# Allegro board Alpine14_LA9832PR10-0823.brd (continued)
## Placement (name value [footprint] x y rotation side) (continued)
PU1  -  [TS5A63157DCKR_SC70-6]  125.72 122.65 180 top
PU51  -  [TPS51225CRUKR_QFN20_3X3]  188.92 143.86 270 top
PU100  -  [G5616ARZ1U_TQFN20_3X3]  175.97 83.47 180 top
PU150  -  [TPS51362RVER_QFN28_4P5X3P5]  150.59 77.32 90 bottom
PU200  -  [SYN470DBC_DFN10_3X3]  267.32 168.04 0 bottom
PU300  -  [TPS51622RSM_QFN32_4X4]  52.87 19.74 270 bottom
PU301  -  [CSD97374CQ4M_SON8_3P5X4P5]  68.88 26.48 270 bottom
PU401  -  [INA199A1DCKR_SC70-6]  116.07 130.98 90 top
PU402  -  [BQ24717RGRR_QFN20_3P5X3P5]  109.84 143.68 0 top
PU403  -  [LM358DR2G_SO8]  109.71 127.91 90 top
PU404  -  [LM393DR_SO8]  112.16 121.47 90 top
PU405  -  [74AHC1G08GW_SOT353-5]  121.32 118.15 90 top
PU500  -  [74AHC1G08GW_SOT353-5]  137.2 131.45 270 top
PU502  -  [74AHC1G08GW_SOT353-5]  140.5 127.64 270 top
PU503  -  [74AHC1G08GW_SOT353-5]  144.86 149.54 0 top
PU504  -  [74AHC1G08GW_SOT353-5]  145.5 152.71 0 top
PU505  -  [74AHC1G08GW_SOT353-5]  141.94 152.71 0 top
PU506  -  [74AHC1G08GW_SOT353-5]  145.76 129.11 0 top
PU600  -  [RT8813AGQW_WQFN24_4X4]  58.46 36.55 270 bottom
PU700  RT8237EZQW(2)_WDFN10_3X3  [RT8237EZQW-2_WDFN10_3X3]  34.68 30.04 90 bottom
PU701  -  [CD3301BRHHR_QFN36_6X6]  121.03 135.77 0 top
Q5  DMN66D0LDW-7_SOT363-6~D  [DMN66D0LDW-7_SOT363-6]  174.61 107.18 180 top
Q9  -  [L2N7002WT1G_SC-70-3]  135.93 116.89 90 top
Q11  PMST3904_SOT323-3~D  [PMST3904_SOT323-3]  116.05 42.5 180 top
Q12  MMST3904-7-F_SOT323-3~D  [MMST3904-7-F_SOT323-3]  149.9 115.5 270 top
Q13  PMST3904_SOT323-3~D  [PMST3904_SOT323-3]  76.05 78.38 180 top
Q14  PMST3904_SOT323-3~D  [PMST3904_SOT323-3]  166.84 142.17 0 top
Q15  PMST3904_SOT323-3~D  [PMST3904_SOT323-3]  174.28 79.25 180 bottom
Q16  PDTA114EU_SC70-3~D  [PDTA114EU_SC70-3]  177.46 8.6 0 top
Q19  DMN66D0LDW-7_SOT363-6~D  [DMN66D0LDW-7_SOT363-6]  84.38 110.92 180 top
Q20  -  [L2N7002WT1G_SC-70-3]  261.09 159.31 270 bottom
Q21  DMN66D0LDW-7_SOT363-6~D  [DMN66D0LDW-7_SOT363-6]  264.31 158.67 0 bottom
Q22  DMN66D0LDW-7_SOT363-6~D  [DMN66D0LDW-7_SOT363-6]  225.78 151.49 90 bottom
Q24  DMN66D0LDW-7_SOT363-6~D  [DMN66D0LDW-7_SOT363-6]  172.88 2.9 90 top
Q26  PDTA114EU_SC70-3~D  [PDTA114EU_SC70-3]  179.33 4.25 90 top
Q28  DMN66D0LDW-7_SOT363-6~D  [DMN66D0LDW-7_SOT363-6]  190.98 88.84 270 top
Q30  DMN66D0LDW-7_SOT363-6~D  [DMN66D0LDW-7_SOT363-6]  227.68 150.18 270 bottom
Q32  DMN66D0LDW-7_SOT363-6~D  [DMN66D0LDW-7_SOT363-6]  192.84 156.71 180 top
Q122  DMN66D0LDW-7_SOT363-6~D  [DMN66D0LDW-7_SOT363-6]  19.08 102.72 90 top
Q123  DMN66D0LDW-7_SOT363-6~D  [DMN66D0LDW-7_SOT363-6]  247.17 148.6 270 bottom
Q124  SI3457CDV-T1-GE3_TSOP6~D  [SI3457CDV-T1-GE3_TSOP6]  86.46 159.09 0 bottom
Q125  DMN66D0LDW-7_SOT363-6~D  [DMN66D0LDW-7_SOT363-6]  88.43 161.87 270 bottom
Q126  -  [LP2301ALT1G_SOT23-3]  101.35 144.01 90 top
Q133  NTS4001NT1G_SC70-3  [BSS138W-7-F_SOT323-3]  149.32 147.95 270 top
Q135  NTS4001NT1G_SC70-3  [BSS138W-7-F_SOT323-3]  155.61 148.07 270 top
Q137  -  [LP2301ALT1G_SOT23-3]  72.49 107.93 0 top
Q138  -  [LP2301ALT1G_SOT23-3]  77.68 103.05 0 bottom
Q140  DMN66D0LDW-7_SOT363-6~D  [DMN66D0LDW-7_SOT363-6]  74.9 107.45 270 bottom
Q142  -  [SI3456DDV-T1-GE3_TSOP6]  95.27 75.55 270 top
Q143  DMN66D0LDW-7_SOT363-6~D  [DMN66D0LDW-7_SOT363-6]  94.97 83.95 270 top
QC1  DMN66D0LDW-7_SOT363-6~D  [DMN66D0LDW-7_SOT363-6]  119.99 83 270 top
QC4  DMN66D0LDW-7_SOT363-6~D  [DMN66D0LDW-7_SOT363-6]  167.69 123.93 90 top
QC6  DMN66D0LDW-7_SOT363-6~D  [DMN66D0LDW-7_SOT363-6]  80.62 91.45 270 bottom
QC8  DMN66D0LDW-7_SOT363-6~D  [DMN66D0LDW-7_SOT363-6]  71.92 94.81 270 top
QC9  DMN66D0LDW-7_SOT363-6~D  [DMN66D0LDW-7_SOT363-6]  69.6 103.6 180 bottom
QC11  DMN66D0LDW-7_SOT363-6~D  [DMN66D0LDW-7_SOT363-6]  70.5 82.23 270 top
QD1  -  [BSS138-G_SOT23-3]  190.6 39.4 0 top
QV2806  DMN66D0LDW-7_SOT363-6~D  [DMN66D0LDW-7_SOT363-6]  24.87 100.18 90 bottom
QZ5  -  [DMN66D0LDW-7_SOT363-6]  29.12 101.45 90 top
QZ21  -  [DMN66D0LDW-7_SOT363-6]  60.94 71.89 270 top
QZ22  -  [DMN66D0LDW-7_SOT363-6]  24.12 93.33 180 top
R1  1K_0402_5%~D  [R_0402]  121.64 71.57 270 bottom
R2  1K_0402_5%~D  [R_0402]  120.75 71.57 270 bottom
R3  0_0402_5%~D  [R_0402]  19.66 18.48 270 bottom
R4  33_0402_5%~D  [R_0402]  17.88 18.48 270 bottom
R5  33_0402_5%~D  [R_0402]  34.26 17.63 90 bottom
R6  33_0402_5%~D  [R_0402]  36.17 18.55 270 bottom
R7  33_0402_5%~D  [R_0402]  20.55 17.57 90 bottom
R8  0_0402_5%~D  [R_0402]  166.91 106.11 270 top
R9  33_0402_5%~D  [R_0402]  26.83 15.92 90 bottom
R10  0_0402_5%~D  [R_0402]  19.66 19.73 90 bottom
R11  33_0402_5%~D  [R_0402]  25.88 17.82 90 bottom
R12  33_0402_5%~D  [R_0402]  26.83 17.82 90 bottom
R13  33_0402_5%~D  [R_0402]  21.44 19.73 90 bottom
R14  0_0402_5%~D  [R_0402]  18.77 18.48 270 bottom
R15  33_0402_5%~D  [R_0402]  16.99 18.48 270 bottom
R16  33_0402_5%~D  [R_0402]  33.31 17.63 90 bottom
R17  0_0402_5%~D  [R_0402]  18.77 19.73 90 bottom
R18  33_0402_5%~D  [R_0402]  20.55 19.73 90 bottom
R19  33_0402_5%~D  [R_0402]  35.22 18.55 270 bottom
R20  33_0402_5%~D  [R_0402]  21.44 17.57 90 bottom
R21  33_0402_5%~D  [R_0402]  25.88 15.92 90 bottom
R22  33_0402_5%~D  [R_0402]  17.88 19.73 90 bottom
R23  0_0402_5%~D  [R_0402]  15.15 14.54 90 bottom
R24  1K_0402_5%~D  [R_0402]  98.97 23.98 90 bottom
R25  100K_0402_5%~D  [R_0402]  173.28 143.31 180 top
R26  100K_0402_5%~D  [R_0402]  220.7 135.58 270 top
R27  100K_0402_5%~D  [R_0402]  3.59 33.44 90 bottom
R28  220K_0402_5%~D  [R_0402]  193.08 39.48 90 top
R29  66.5_0402_1%  [R_0402]  189.98 43.23 180 top
R30  66.5_0402_1%  [R_0402]  189.98 44.19 180 top
R31  66.5_0402_1%  [R_0402]  189.98 45.14 180 top
R32  2M_0402_5%~D  [R_0402]  193.08 42.17 270 top
R33  66.5_0402_1%  [R_0402]  189.98 46.09 180 top
R34  0_0402_5%~D  [R_0402]  190.85 33 90 top
R35  10K_0402_5%~D  [R_0402]  154.49 107.24 180 top
R36  100K_0402_5%~D  [R_0402]  175.74 106.18 270 top
R37  0_0402_5%~D  [R_0402]  159.54 139.63 0 top
R38  0_0402_5%  [R0402_0OHM]  128.19 86.82 270 top
R39  20K_0402_1%~D  [R_0402]  261.77 150.11 0 bottom
R40  2.7K_0402_5%~D  [R_0402]  113.02 102.8 180 top
R41  33_0402_5%~D  [R_0402]  16.99 19.73 90 bottom
R42  2.7K_0402_5%~D  [R_0402]  113.02 104.58 180 top
R43  33_0402_5%~D  [R_0402]  33.31 20.71 270 bottom
R44  1M_0402_5%~D  [R_0402]  123.29 112.18 90 top
R45  33_0402_5%~D  [R_0402]  22.33 18.48 270 bottom
R46  2.2K_0402_5%~D  [R_0402]  112.11 108.08 270 top
R47  1M_0402_5%~D  [R_0402]  124.18 112.18 90 top
R48  33_0402_5%~D  [R_0402]  34.26 20.71 270 bottom
R49  2.2K_0402_5%~D  [R_0402]  112.24 108.94 90 top
R50  0_0402_5%~D  [R_0402]  158.29 136.64 180 top
R51  0_0402_5%~D  [R_0402]  158.29 135.75 180 top
R52  0_0402_5%~D  [R_0402]  82.55 124.74 90 bottom
R53  0_0402_5%  [R0402_0OHM]  128.19 84.72 270 top
R54  2.7K_0402_5%~D  [R_0402]  127.53 110.1 0 top
R55  2.2K_0402_5%~D  [R_0402]  115.54 96.9 270 top
R56  0_0402_5%~D  [R_0402]  157.39 134.5 270 top
R57  33_0402_5%~D  [R_0402]  29.69 12.36 90 bottom
R58  33_0402_5%~D  [R_0402]  35.22 20.71 270 bottom
R59  33_0402_5%~D  [R_0402]  36.17 20.71 270 bottom
R60  0_0402_5%~D  [R_0402]  158.28 134.5 270 top
R61  0_0402_5%~D  [R_0402]  166.74 134.8 180 top
R62  0_0402_5%~D  [R_0402]  166.74 133.91 180 top
R63  0_0402_5%  [R0402_0OHM]  129.91 86.21 270 top
R64  10K_0402_5%~D  [R_0402]  97.57 86.4 90 top
R65  2.2K_0402_5%~D  [R_0402]  96.56 86.4 90 top
R66  1M_0402_5%~D  [R_0402]  125.88 96.76 0 top
R67  0_0402_5%~D  [R_0402]  166.74 132.13 180 top
R68  0_0402_5%~D  [R_0402]  166.74 133.02 180 top
R69  1M_0402_5%~D  [R_0402]  116.43 96.9 270 top
R70  0_0402_5%~D  [R_0402]  156.83 90.22 0 top
R71  0_0402_5%~D  [R_0402]  118.83 13.64 0 bottom
R72  0_0402_5%~D  [R_0402]  158.79 88.46 180 top
R73  0_0402_5%~D  [R_0402]  110.6 87.5 90 top
R74  2.7K_0402_5%~D  [R_0402]  128.45 99.11 180 top
R75  0_0402_5%~D  [R_0402]  112.42 87.5 90 top
R76  0_0402_5%~D  [R_0402]  111.49 87.5 90 top
R77  0_0402_5%~D  [R_0402]  158.51 123.16 180 top
R78  0_0402_5%~D  [R_0402]  158.75 89.31 90 top
R79  0_0402_5%~D  [R_0402]  156.83 89.33 0 top
R91  1M_0402_5%~D  [R_0402]  113.97 107.69 180 top
R92  1M_0402_5%~D  [R_0402]  113.97 106.8 180 top
R93  0_0402_5%~D  [R_0402]  118.83 12.75 0 bottom
R94  0_0402_5%~D  [R_0402]  118.83 10.98 0 bottom
R95  0_0402_5%~D  [R_0402]  118.83 11.87 0 bottom
R96  0_0402_5%~D  [R_0402]  117.59 11.87 180 bottom
R97  0_0402_5%~D  [R_0402]  117.59 10.98 180 bottom
R98  0_0402_5%~D  [R_0402]  117.59 13.64 180 bottom
R99  0_0402_5%~D  [R_0402]  117.59 12.75 180 bottom
R100  0_0402_5%~D  [R_0402]  92.49 57.57 90 bottom
R101  0_0402_5%~D  [R_0402]  91.6 57.57 90 bottom
R102  0_0402_5%~D  [R_0402]  98.73 53.46 180 bottom
R104  0_0402_5%~D  [R_0402]  98.73 54.66 180 bottom
R105  0_0402_5%~D  [R_0402]  94.51 61.46 0 bottom
R106  0_0402_5%~D  [R_0402]  94.51 60.57 0 bottom
R107  0_0402_5%  [R0402_0OHM]  124.69 95.42 90 top
R108  100K_0402_5%~D  [R_0402]  97.89 83.04 90 top
R109  10K_0402_5%~D  [R_0402]  93.81 81.53 0 top
R110  0_0402_5%~D  [R_0402]  96.05 94.59 90 top
R120  1M_0402_5%~D  [R_0402]  147.35 172.17 270 top
R121  1M_0402_5%~D  [R_0402]  147.44 163.85 0 top
R122  10K_0402_5%~D  [R_0402]  163.25 128.45 180 top
R123  10K_0402_5%~D  [R_0402]  162.66 127.45 270 top
R124  10K_0402_5%~D  [R_0402]  85.7 111.57 270 top
R125  100K_0402_5%~D  [R_0402]  83.1 112.91 270 top
R126  100K_0402_5%~D  [R_0402]  85.27 107.94 180 top
R130  0_0805_5%  [R0805_0OHM]  240.96 157.24 270 top
R136  33_0402_5%~D  [R_0402]  256.19 159.33 270 bottom
R137  22_0402_5%~D  [R_0402]  200.81 165.92 0 bottom
R139  22_0402_5%~D  [R_0402]  200.81 163.44 0 bottom
R141  33_0402_5%~D  [R_0402]  199.03 165.28 0 bottom
R142  0_0402_5%~D  [R_0402]  243.69 155.13 270 bottom
R143  0_0402_5%  [R0402_0OHM]  199.03 164.01 0 bottom
R144  0_0402_5%  [R0402_0OHM]  200.81 164.65 0 bottom
R148  47_0402_5%~D  [R_0402]  254.29 158.41 90 bottom
R149  33_0402_5%~D  [R_0402]  255.18 158.41 90 bottom
R150  10K_0402_5%~D  [R_0402]  246.29 156.28 270 bottom
R152  39.2K_0402_1%~D  [R_0402]  261.07 156.9 0 bottom
R153  0_0402_5%  [R0402_0OHM]  244.64 155.13 270 bottom
R154  0_0402_5%  [R0402_0OHM]  249.71 172.9 0 top
R155  0_0402_5%  [R0402_0OHM]  82.92 86.86 180 bottom
R156  39.2K_0402_1%~D  [R_0402]  264.2 154.85 90 bottom
R157  20K_0402_1%~D  [R_0402]  266.74 157.84 90 bottom
R158  100K_0402_5%~D  [R_0402]  265.86 159.76 180 bottom
R159  100K_0402_5%~D  [R_0402]  265.08 154.85 90 bottom
R160  10K_0402_5%~D  [R_0402]  257.29 161.28 180 bottom
R161  100K_0402_5%~D  [R_0402]  150.47 148.34 270 top
R162  18_0402_5%  [R_0402]  264.63 149.79 0 bottom
R163  100K_0402_5%~D  [R_0402]  264.13 161.27 90 bottom
R164  100K_0402_5%~D  [R_0402]  154.48 149.79 180 top
R165  0_0402_5%  [R0402_0OHM]  82.92 85.4 180 bottom
R166  18_0402_5%  [R_0402]  264.63 148.83 0 bottom
R167  10K_0402_5%~D  [R_0402]  258.22 163.06 0 bottom
R168  10K_0402_5%~D  [R_0402]  104.01 3.1 180 bottom
R169  0_0402_5%  [R0402_0OHM]  172.68 135.37 0 top
R170  10K_0402_5%~D  [R_0402]  104.27 5.41 180 bottom
R171  10K_0402_5%~D  [R_0402]  177.01 145.1 270 top
R172  10K_0402_5%~D  [R_0402]  176.06 145.1 270 top
R175  0_0402_5%  [R0402_0OHM]  177.45 132.5 90 top
R176  4.7K_0402_5%~D  [R_0402]  174.54 134.18 270 top
R178  4.7K_0402_5%~D  [R_0402]  174.55 132.39 180 top
R179  0_0402_5%  [R0402_0OHM]  173.65 133.26 90 top
R180  0_0402_5%  [R0402_0OHM]  176.5 132.5 90 top
R181  0_0603_5%~D  [R0603_0OHM]  185.46 133.28 90 top
R183  0_0402_5%  [R0402_0OHM]  180.25 131.61 90 top
R184  1K_0402_5%~D  [R_0402]  179.36 144.19 90 top
R185  3.01K_0402_1%~D  [R_0402]  183.87 134.31 270 top
R187  2.2K_0402_5%  [R_0402]  257.15 146.82 270 bottom
R193  0_0402_5%  [R0402_0OHM]  167.69 110.86 180 top
R197  2.2K_0402_5%  [R_0402]  256.26 146.82 270 bottom
R201  0_0402_5%~D  [R_0402]  174.18 148.37 270 top
R205  191_0402_1%~D  [R_0402]  14.51 22.58 90 bottom
R206  1M_0402_5%~D  [R_0402]  180.24 133.4 0 top
R208  100K_0402_5%~D  [R_0402]  245.34 150.63 270 bottom
R211  4.7K_0402_1%~D  [R_0402]  9.81 33.76 90 bottom
R212  100K_0402_5%~D  [R_0402]  5.99 27.17 0 bottom
R214  100K_0402_5%~D  [R_0402]  6.91 28.06 180 bottom
R215  0_0402_5%~D  [R_0402]  275.92 161.11 0 bottom
R216  2.2K_0402_5%~D  [R_0402]  223 142.68 180 bottom
R217  2.2K_0402_5%~D  [R_0402]  223 145.34 180 bottom
R218  0_0402_5%~D  [R_0402]  222.08 143.56 0 bottom
R219  0_0402_5%~D  [R_0402]  222.08 144.45 0 bottom
R223  0_0402_5%  [R0402_0OHM]  298.63 155.5 180 top
R224  0_0402_5%~D  [R_0402]  293.79 152.85 270 top
R225  0_0402_5%~D  [R_0402]  298.63 156.46 180 top
R226  100K_0402_5%~D  [R_0402]  224.7 148.82 90 bottom
R227  100K_0402_5%~D  [R_0402]  224.7 151.36 90 bottom
R228  0_0402_5%~D  [R_0402]  282.8 159.43 90 bottom
R229  100K_0402_5%~D  [R_0402]  228.7 150.18 270 bottom
R230  10_0402_5%~D  [R_0402]  16.98 27.55 0 bottom
R231  0_0402_5%  [R0402_0OHM]  20.74 34.97 90 bottom
R232  2.7K_0402_5%~D  [R_0402]  113.02 103.69 180 top
R233  0_0402_5%  [R0402_0OHM]  281.85 159.43 90 bottom
R234  0_0402_5%  [R0402_0OHM]  278.8 159.68 90 bottom
R236  0_0402_5%  [R0402_0OHM]  277.91 159.68 90 bottom
R238  0_0402_5%  [R0402_0OHM]  272.83 159.68 90 bottom
R239  0_0402_5%  [R0402_0OHM]  273.79 159.68 90 bottom
R240  0_0402_5%  [R0402_0OHM]  274.74 159.68 90 bottom
R241  0_0402_5%  [R0402_0OHM]  283.76 160.34 270 bottom
R244  0_0402_5%  [R0402_0OHM]  284.71 160.34 270 bottom
R246  0_0402_5%~D  [R_0402]  22.08 73.27 180 bottom
R247  0_0402_5%~D  [R_0402]  22.08 74.16 180 bottom
R248  0_0402_5%~D  [R_0402]  21.83 75.05 180 bottom
R249  0_0402_5%~D  [R_0402]  22.82 75.52 180 top
R250  0_0402_5%~D  [R_0402]  21.83 75.94 180 bottom
R251  0_0402_5%~D  [R_0402]  22.82 76.54 180 top
R252  0_0402_5%  [R0402_0OHM]  149.71 159.68 90 bottom
R253  0_0402_5%  [R0402_0OHM]  150.72 159.68 90 bottom
R254  0_0402_5%  [R0402_0OHM]  150.72 160.6 270 top
R255  0_0402_5%  [R0402_0OHM]  151.61 159.68 90 bottom
R256  0_0402_5%  [R0402_0OHM]  151.61 160.6 270 top
R257  0_0402_5%  [R0402_0OHM]  152.63 159.68 90 bottom
R258  0_0402_5%  [R0402_0OHM]  154.53 160.6 270 top
R259  0_0402_5%  [R0402_0OHM]  148.82 159.68 90 bottom
R260  0_0402_5%  [R0402_0OHM]  148.82 160.6 270 top
R261  0_0402_5%  [R0402_0OHM]  149.71 160.6 270 top
R262  0_0402_5%  [R0402_0OHM]  152.63 160.6 270 top
R263  0_0402_5%  [R0402_0OHM]  153.52 159.68 90 bottom
R264  0_0402_5%  [R0402_0OHM]  153.52 160.6 270 top
R265  0_0402_5%  [R0402_0OHM]  154.53 159.68 90 bottom
R266  0_0402_5%  [R0402_0OHM]  155.42 159.68 90 bottom
R267  0_0402_5%  [R0402_0OHM]  155.42 160.6 270 top
R268  100K_0402_5%~D  [R_0402]  156.33 159.67 90 bottom
R269  0_0402_5%  [R0402_0OHM]  163.87 167.36 90 top
R270  0_0402_5%  [R0402_0OHM]  164.88 167.36 90 top
R271  100K_0402_5%~D  [R_0402]  157.15 171.57 0 top
R272  10K_0402_5%~D  [R_0402]  182.25 172 180 top
R273  33_0402_5%~D  [R_0402]  178.66 165.68 270 top
R274  0_0402_5%  [R0402_0OHM]  167.8 167.36 90 top
R275  0_0402_5%  [R0402_0OHM]  169.77 167.36 90 top
R276  0_0402_5%  [R0402_0OHM]  168.82 167.36 90 top
R277  0_0402_5%  [R0402_0OHM]  170.73 167.36 90 top
R282  100K_0402_5%~D  [R_0402]  162.15 88.5 90 top
R283  100K_0402_5%~D  [R_0402]  175.31 93.65 180 top
R284  100K_0402_5%~D  [R_0402]  170.22 106.11 270 top
R285  100K_0402_5%~D  [R_0402]  163.04 88.5 90 top
R286  100K_0402_5%~D  [R_0402]  175.31 95.49 180 top
R288  10K_0402_5%~D  [R_0402]  163.93 88.5 90 top
R289  100K_0402_5%~D  [R_0402]  172.12 106.11 270 top
R290  33_0402_5%~D  [R_0402]  160.5 108.21 270 top
R291  10K_0402_5%~D  [R_0402]  166.72 88.5 90 top
R292  100K_0402_5%~D  [R_0402]  175.31 94.54 180 top
R293  100K_0402_5%~D  [R_0402]  158.52 105.15 0 top
R294  0_0402_5%  [R0402_0OHM]  175.28 103.43 0 top
R295  100K_0402_5%~D  [R_0402]  165.83 88.51 90 top
R296  10K_0402_5%~D  [R_0402]  156.77 87.34 90 top
R297  0_0402_5%  [R0402_0OHM]  19.72 34.97 90 bottom
R298  100K_0402_5%~D  [R_0402]  166.02 106.12 270 top
R299  1M_0402_5%~D  [R_0402]  35.93 55.16 90 bottom
R302  100K_0402_5%~D  [R_0402]  179.03 91.88 0 top
R303  100K_0402_5%~D  [R_0402]  168.12 106.11 270 top
R304  10K_0402_5%~D  [R_0402]  177.85 95.24 180 top
R305  100K_0402_5%~D  [R_0402]  161.52 106.11 270 top
R306  0_0402_5%  [R0402_0OHM]  18.52 34.97 90 bottom
R307  100K_0402_5%~D  [R_0402]  158.08 93.78 0 top
R308  100K_0402_5%~D  [R_0402]  176.2 101.72 180 top
R309  100K_0402_5%~D  [R_0402]  164.88 88.51 90 top
R310  10K_0402_5%~D  [R_0402]  170.85 88.5 90 top
R311  150_0402_1%~D  [R_0402]  129.39 103.06 270 top
R312  150_0402_1%~D  [R_0402]  129.39 103.93 90 top
R313  100K_0402_5%~D  [R_0402]  169.96 88.51 90 top
R315  0_0402_5%  [R0402_0OHM]  17.5 34.97 90 bottom
R316  0_0402_5%  [R0402_0OHM]  173.07 89.13 90 top
R317  100K_0402_5%~D  [R_0402]  175.28 99.94 0 top
R318  0_0402_5%  [R0402_0OHM]  165.13 106.12 270 top
R319  0_0402_5%  [R0402_0OHM]  158.52 104.19 0 top
R320  100K_0402_5%~D  [R_0402]  176.2 100.83 180 top
R321  1K_0402_5%~D  [R_0402]  159.44 103.24 180 top
R322  100K_0402_5%~D  [R_0402]  178.1 91.89 180 top
R324  33_0402_5%~D  [R_0402]  158.99 96.46 180 top
R325  10_0402_1%~D  [R_0402]  178.1 92.78 180 top
R326  1K_0402_5%~D  [R_0402]  169.01 105.2 90 top
R327  100K_0402_5%~D  [R_0402]  139.53 93.08 0 top
R328  100K_0402_5%~D  [R_0402]  137.2 94.72 90 top
R329  10K_0402_5%~D  [R_0402]  140.14 92.13 180 top
R330  10K_0402_5%~D  [R_0402]  138.07 96.51 0 top
R331  10K_0402_5%~D  [R_0402]  175.17 146.24 270 top
R332  0_0402_5%  [R0402_0OHM]  133.37 101.85 0 top
R333  0_0402_5%  [R0402_0OHM]  15.21 34.97 90 bottom
R334  0_0402_5%  [R0402_0OHM]  139.04 116.25 90 top
R335  10K_0402_5%~D  [R_0402]  140.44 115.36 90 top
R336  0_0402_5%  [R0402_0OHM]  154.49 100.7 180 top
R337  0_0402_5%  [R0402_0OHM]  16.23 34.97 90 bottom
R338  1K_0402_5%~D  [R_0402]  142.98 89.86 270 top
R340  10K_0402_5%~D  [R_0402]  149.02 112.78 270 top
R341  0_0402_5%  [R0402_0OHM]  16.98 25.77 0 bottom
R342  100K_0402_5%~D  [R_0402]  141.32 115.36 90 top
R343  100K_0402_5%~D  [R_0402]  154.66 95.29 90 top
R349  1K_0402_5%~D  [R_0402]  136.89 108.58 180 top
R351  150_0402_1%~D  [R_0402]  127.53 106.29 0 top
R352  1K_0402_5%~D  [R_0402]  142.09 93.79 270 top
R353  100K_0402_5%~D  [R_0402]  150.79 112.78 270 top
R354  10K_0402_5%~D  [R_0402]  176.01 97.4 180 top
R358  100K_0402_5%~D  [R_0402]  142.09 91.1 90 top
R360  100K_0402_5%~D  [R_0402]  132.93 121.93 90 top
R362  100K_0402_5%~D  [R_0402]  142.09 89.86 270 top
R363  100K_0402_5%~D  [R_0402]  148.13 112.78 270 top
R366  10K_0402_5%~D  [R_0402]  143.93 114.6 90 top
R367  1K_0402_5%~D  [R_0402]  134.3 99.12 180 top
R370  100K_0402_5%~D  [R_0402]  134.3 100 180 top
R371  100K_0402_5%~D  [R_0402]  154.49 108.13 180 top
R373  8.2K_0402_5%~D  [R_0402]  147.88 115.64 270 top
R374  0_0402_5%  [R0402_0OHM]  136.71 111.31 180 top
R375  43_0402_5%~D  [R_0402]  135.61 113.39 90 top
R376  10K_0402_5%~D  [R_0402]  154.48 97.08 180 top
R378  0_0402_5%  [R0402_0OHM]  136.25 95.1 90 top
R379  0_0402_5%  [R0402_0OHM]  136.63 98.72 90 top
R380  100K_0402_5%~D  [R_0402]  133.12 103.81 0 top
R381  4.7K_0402_5%~D  [R_0402]  130.66 105.01 90 top
R382  10_0402_1%~D  [R_0402]  153.58 111.69 0 top
R383  1K_0402_5%~D  [R_0402]  153.58 109.91 0 top
R384  100_0402_1%~D  [R_0402]  136.18 104.4 270 top
R386  1K_0402_5%~D  [R_0402]  143.93 91.93 90 top
R387  100K_0402_5%~D  [R_0402]  257.29 163.06 180 bottom
R388  49.9_0402_1%~D  [R_0402]  148.27 120.12 0 top
R389  100K_0402_5%~D  [R_0402]  73.57 81.32 90 top
R391  100K_0402_5%~D  [R_0402]  166.14 107.5 0 top
R392  8.2K_0402_5%~D  [R_0402]  143.93 89.86 270 top
R393  10K_0402_5%~D  [R_0402]  136.99 91.05 0 top
R394  1.58K_0402_1%  [R_0402]  153.57 97.97 0 top
R395  10K_0402_5%~D  [R_0402]  148.27 124.76 0 top
R396  10K_0402_5%~D  [R_0402]  147.39 125.7 90 top
R397  10K_0402_5%~D  [R_0402]  149.18 128.5 180 top
R398  100K_0402_5%~D  [R_0402]  148.27 125.64 0 top
R399  10K_0402_5%~D  [R_0402]  136.99 91.94 0 top
R400  0_0402_5%  [R0402_0OHM]  149.18 126.6 180 top
R402  8.2K_0402_5%~D  [R_0402]  154.48 113.47 180 top
R403  2.2K_0402_5%~D  [R_0402]  148.79 115.66 270 top
R404  4.7K_0402_5%~D  [R_0402]  181.51 100.13 0 top
R405  4.7K_0402_5%~D  [R_0402]  179.63 100.13 180 top
R406  0_0402_5%  [R0402_0OHM]  149.18 127.55 180 top
R407  0_0402_5%  [R0402_0OHM]  166.85 167.36 90 top
R408  10K_0402_5%~D  [R_0402]  154.49 106.35 180 top
R410  0_0402_5%  [R0402_0OHM]  16.98 26.66 0 bottom
R411  33_0402_5%~D  [R_0402]  144.24 120.31 90 top
R413  0_0402_5%  [R0402_0OHM]  142.28 120.31 90 top
R414  0_0402_5%~D  [R_0402]  143.23 120.31 90 top
R415  0_0402_5%  [R0402_0OHM]  165.84 167.36 90 top
R416  0_0402_5%  [R0402_0OHM]  86.71 73.9 0 top
R417  0_0402_5%~D  [R_0402]  86.66 72.98 0 top
R418  0_0402_5%  [R0402_0OHM]  86.71 72.04 0 top
R419  100K_0402_5%~D  [R_0402]  163.29 106.11 270 top
R421  0_0402_5%~D  [R_0402]  84.49 26.61 270 top
R422  0_0402_5%  [R0402_0OHM]  82.84 26.61 270 top
R423  0_0402_5%~D  [R_0402]  85.38 26.61 270 top
R424  0_0402_5%  [R0402_0OHM]  86.27 26.61 270 top
R425  0_0402_5%~D  [R_0402]  211.48 149.79 0 top
R426  0_0402_5%  [R0402_0OHM]  211.48 150.68 0 top
R428  10K_0402_5%~D  [R_0402]  175.42 3.81 270 top
R429  300_0402_5%  [R_0402]  194.28 45.34 270 top
R432  100K_0402_5%~D  [R_0402]  175.36 4.74 90 top
R433  300_0402_5%  [R_0402]  193.39 45.34 270 top
R435  300_0402_5%  [R_0402]  181.7 8.5 0 top
R436  300_0402_5%  [R_0402]  189.84 88.84 270 top
R438  300_0402_5%  [R_0402]  178.41 4.26 270 top
R440  10K_0402_5%~D  [R_0402]  139.99 117.96 90 top
R441  0_0402_5%  [R0402_0OHM]  181.51 101.02 0 top
R443  0_0402_5%  [R0402_0OHM]  6.42 34.16 180 bottom
R444  0_0402_5%  [R0402_0OHM]  179.63 101.02 180 top
R449  0_0402_5%~D  [R_0402]  179.63 101.97 180 top
R450  0_0402_5%~D  [R_0402]  181.51 101.97 0 top
R459  100K_0402_5%~D  [R_0402]  113.5 69.41 180 top
R460  10K_0402_5%~D  [R_0402]  25.12 92.78 270 top
R461  0_0402_5%  [R0402_0OHM]  136.04 100.64 0 top
R462  680_0402_1%  [R_0402]  19.68 100.27 270 bottom
R463  680_0402_1%  [R_0402]  19.68 101.13 90 bottom
R464  680_0402_1%  [R_0402]  18.73 97.98 270 bottom
R465  680_0402_1%  [R_0402]  19.68 93.54 270 bottom
R466  680_0402_1%  [R_0402]  18.73 98.85 90 bottom
R467  680_0402_1%  [R_0402]  19.68 95.7 270 bottom
R468  680_0402_1%  [R_0402]  18.8 94.09 90 bottom
R469  680_0402_1%  [R_0402]  19.68 96.56 90 bottom
R470  2.2K_0402_5%~D  [R_0402]  20.28 104 0 top
R471  2.2K_0402_5%~D  [R_0402]  15.72 102.72 90 top
R472  0_0402_5%~D  [R_0402]  23.09 103.99 180 top
R473  10K_0402_5%~D  [R_0402]  14.83 103.64 270 top
R474  20K_0402_5%~D  [R_0402]  24.18 90.42 180 top
R475  1M_0402_5%~D  [R_0402]  23.99 94.42 180 top
R476  10K_0402_5%~D  [R_0402]  313.16 154.41 90 bottom
R477  10K_0402_5%~D  [R_0402]  177.77 157.27 90 top
R478  10K_0402_5%~D  [R_0402]  183.23 6.35 270 top
R479  10K_0402_5%~D  [R_0402]  281.09 165.42 270 bottom
R480  10K_0402_5%~D  [R_0402]  223.24 150.75 270 bottom
R481  10K_0402_5%~D  [R_0402]  162.41 105.2 90 top
R482  0_0402_5%  [R0402_0OHM]  223.44 146.36 180 bottom
R483  0_0402_5%  [R0402_0OHM]  223.44 147.31 180 bottom
R484  100K_0402_5%~D  [R_0402]  164.18 106.11 270 top
R485  0_0402_5%~D  [R_0402]  102.21 3.09 90 bottom
R486  0_0402_5%  [R0402_0OHM]  95.41 20.2 270 bottom
R487  0_0402_5%  [R0402_0OHM]  96.3 20.2 270 bottom
R488  0_0402_5%~D  [R_0402]  104.01 4.01 180 bottom
R490  10K_0402_5%~D  [R_0402]  91.56 76.43 180 top
R491  2.2K_0402_5%~D  [R_0402]  137.45 114.3 270 top
R492  2.2K_0402_5%~D  [R_0402]  138.34 114.3 270 top
R556  4.7K_0402_5%~D  [R_0402]  161.09 148.45 180 top
R734  0_0402_5%  [R0402_0OHM]  91.03 26.67 270 top
R741  0_0402_5%  [R0402_0OHM]  187.21 106.14 225 top
R742  0_0402_5%  [R0402_0OHM]  187.84 105.51 225 top
R2576  100K_0402_5%~D  [R_0402]  89.64 157.01 90 bottom
R2577  100K_0402_5%~D  [R_0402]  107.35 103.04 90 top
R2578  47K_0402_5%~D  [R_0402]  89.64 159.05 90 bottom
R2579  0_0402_5%  [R0402_0OHM]  101.02 133.91 180 top
R2580  0_0402_5%  [R0402_0OHM]  101.02 134.8 180 top
R2581  100K_0402_5%~D  [R_0402]  99.73 99.7 270 top
R2582  2.2K_0402_5%~D  [R_0402]  98.21 109.6 270 top
R2583  12K_0402_1%  [R_0402]  108.7 108.07 180 top
R2584  2.2K_0402_5%~D  [R_0402]  97.32 109.6 270 top
R2585  10K_0402_5%~D  [R_0402]  101.7 132.12 90 top
R2586  100K_0402_5%~D  [R_0402]  97.86 102.21 270 top
R2588  0_0402_5%  [R0402_0OHM]  80.49 91.42 90 top
R2590  4.7K_0402_5%~D  [R_0402]  94.27 103.32 270 top
R2591  4.7K_0402_5%~D  [R_0402]  96.94 103.32 270 top
R2592  4.7K_0402_5%~D  [R_0402]  95.16 102.4 90 top
R2593  4.7K_0402_5%~D  [R_0402]  96.05 102.4 90 top
R2594  0_0402_5%  [R0402_0OHM]  79.6 91.42 90 top
R2595  0_0402_5%  [R0402_0OHM]  100.8 139.75 0 top
R2596  0_0402_5%  [R0402_0OHM]  104.05 137.86 270 top
R2597  0_0402_5%  [R0402_0OHM]  109.51 105.79 270 top
R2598  0_0402_5%  [R0402_0OHM]  108.62 105.79 270 top
R2599  0_0402_5%  [R0402_0OHM]  89.38 116.78 270 top
R2600  0_0402_5%  [R0402_0OHM]  90.27 116.78 270 top
R2601  0_0402_5%~D  [R_0402]  112.05 95.76 270 top
R2602  0_0402_5%  [R0402_0OHM]  111.16 95.76 270 top
R2605  47K_0402_5%~D  [R_0402]  71.81 108.32 180 bottom
R2626  2K_0402_5%  [R_0402]  300.77 165.61 270 top
R2627  4.7K_0402_5%~D  [R_0402]  294.35 166.93 0 top
R2628  4.7K_0402_5%~D  [R_0402]  298.1 164.7 90 top
R2629  4.7K_0402_5%~D  [R_0402]  299.88 164.7 90 top
R2630  4.7K_0402_5%~D  [R_0402]  298.99 164.7 90 top
R2631  4.7K_0402_5%~D  [R_0402]  301.66 164.7 90 top
R2633  4.7K_0402_5%~D  [R_0402]  301.71 174.76 270 top
R2634  4.7K_0402_5%~D  [R_0402]  299.05 174.76 270 top
R2635  4.7K_0402_5%~D  [R_0402]  300.82 174.76 270 top
R2636  4.7K_0402_5%~D  [R_0402]  299.94 174.76 270 top
R2637  4.7K_0402_5%~D  [R_0402]  297.28 174.76 270 top
R2638  4.7K_0402_5%~D  [R_0402]  298.16 173.84 90 top
R2639  4.7K_0402_5%~D  [R_0402]  297.29 163.37 180 top
R2644  4.53K_0402_1%  [R_0402]  302.55 165.61 270 top
R2646  0_0402_5%~D  [R_0402]  295.26 168.77 180 bottom
R2647  0_0402_5%~D  [R_0402]  295.26 167.89 180 bottom
R2648  0_0402_5%~D  [R_0402]  303.44 171.36 90 bottom
R2649  0_0402_5%~D  [R_0402]  304.33 171.36 90 bottom
R2650  0_0402_5%~D  [R_0402]  305.04 169.85 180 bottom
R2651  0_0402_5%~D  [R_0402]  305.04 168.96 180 bottom
R2652  0_0402_5%~D  [R_0402]  294.35 169.79 0 bottom
R2653  0_0402_5%~D  [R_0402]  294.35 170.68 0 bottom
R2654  0_0402_5%  [R0402_0OHM]  305.04 169.85 180 top
R2655  0_0402_5%  [R0402_0OHM]  305.04 168.96 180 top
R2656  0_0402_5%  [R0402_0OHM]  303.44 171.36 90 top
R2657  0_0402_5%  [R0402_0OHM]  304.33 171.36 90 top
R2658  0_0402_5%~D  [R_0402]  157.39 131.42 90 top
R2659  0_0402_5%~D  [R_0402]  158.28 131.42 90 top
R2660  0_0402_5%~D  [R_0402]  155.22 136.64 0 top
R2661  0_0402_5%~D  [R_0402]  155.22 135.75 0 top
R2662  0_0402_5%~D  [R_0402]  167.98 133.02 0 top
R2663  0_0402_5%~D  [R_0402]  167.98 132.13 0 top
R2664  0_0402_5%~D  [R_0402]  167.98 133.91 0 top
R2665  0_0402_5%~D  [R_0402]  167.98 134.8 0 top
R2678  100K_0402_5%~D  [R_0402]  92.63 96.32 180 top
R2688  BLM18PG330SN1_2P  [MURAT_BLM18PG330SN1D_2P]  202.73 121.85 180 top
R2689  12K_0402_1%~D  [R_0402]  174.97 116.07 0 top
R2691  10K_0402_5%~D  [R_0402]  165.4 121.59 180 top
R2692  10K_0402_5%~D  [R_0402]  165.4 122.55 180 top
R2693  10K_0402_5%~D  [R_0402]  166.79 126.47 90 top
R2694  0_0402_5%  [R0402_0OHM]  167.35 115.05 0 top
R2695  100K_0402_5%~D  [R_0402]  164.49 120.7 0 top
R2696  100K_0402_5%~D  [R_0402]  166.34 122.69 270 top
R2697  0_0402_5%  [R0402_0OHM]  167.35 115.94 0 top
R2698  100K_0402_5%~D  [R_0402]  165.9 127.38 270 top
R2699  0_0402_5%  [R0402_0OHM]  166.29 119.75 180 top
R2700  10K_0402_5%~D  [R_0402]  165.39 118.88 270 top
R2701  10K_0402_5%~D  [R_0402]  167.63 117.97 180 top
R2702  BLM18PG330SN1_2P  [MURAT_BLM18PG330SN1D_2P]  202.73 123.75 180 top
R2703  BLM18PG330SN1_2P  [MURAT_BLM18PG330SN1D_2P]  202.73 125.59 180 top
R2704  BLM18PG330SN1_2P  [MURAT_BLM18PG330SN1D_2P]  202.73 127.5 180 top
R2705  3.74K_0402_1%  [R_0402]  127.53 101.91 0 top
RC1  330K_0402_1%~D  [R_0402]  132.74 67.36 0 bottom
RC2  330K_0402_1%~D  [R_0402]  132.74 66.48 0 bottom
RC3  1K_0402_1%~D  [R_0402]  139.23 73.19 90 bottom
RC4  0_0402_5%  [R0402_0OHM]  130.77 72.51 0 bottom
RC5  10M_0402_5%~D  [R_0402]  132.55 73.08 0 bottom
RC6  20K_0402_5%~D  [R_0402]  145.66 73.97 180 bottom
RC7  1M_0402_5%~D  [R_0402]  132.69 66.53 90 top
RC8  20K_0402_5%~D  [R_0402]  146.71 73.97 0 bottom
RC9  1K_0402_1%~D  [R_0402]  138.34 73.19 90 bottom
RC10  1K_0402_1%~D  [R_0402]  102.67 16.31 180 bottom
RC11  100K_0402_5%~D  [R_0402]  119.23 73.38 90 bottom
RC12  10K_0402_5%~D  [R_0402]  122.02 73.32 90 bottom
RC14  0_0402_5%  [R0402_0OHM]  100.56 63.06 270 bottom
RC16  0_0603_5%~D  [R0603_0OHM]  113 13.58 180 bottom
RC17  51_0402_1%~D  [R_0402]  101.75 19.1 0 bottom
RC18  51_0402_1%~D  [R_0402]  102.67 17.2 180 bottom
RC19  3.01K_0402_1%~D  [R_0402]  101.45 62.14 90 bottom
RC20  51_0402_1%~D  [R_0402]  113.12 16.5 0 bottom
RC22  51_0402_1%~D  [R_0402]  101.82 12.56 0 bottom
RC23  33_0402_5%~D  [R_0402]  141.02 73.27 180 bottom
RC24  33_0402_5%~D  [R_0402]  133.53 63.55 180 top
RC25  33_0402_5%~D  [R_0402]  133.65 65.52 180 bottom
RC26  33_0402_5%~D  [R_0402]  133.65 63.68 180 bottom
RC27  10K_0402_5%~D  [R_0402]  124.81 71.7 270 bottom
RC28  2.2K_0402_5%~D  [R_0402]  124.21 81.97 180 top
RC30  2.2K_0402_5%~D  [R_0402]  120.83 80.7 180 top
RC32  0_0402_5%~D  [R_0402]  100.13 108.2 180 top
RC33  0_0402_5%  [R0402_0OHM]  107.35 105.79 270 top
RC36  2.2K_0402_5%~D  [R_0402]  122.72 78.13 90 bottom
RC37  2.2K_0402_5%~D  [R_0402]  121.76 78.13 90 bottom
RC38  0_0402_5%  [R0402_0OHM]  133.5 83.32 0 top
RC40  0_0402_5%  [R0402_0OHM]  100.56 49.85 270 bottom
RC44  1M_0402_5%~D  [R_0402]  100.56 51.63 270 bottom
RC45  3.01K_0402_1%~D  [R_0402]  100.43 53.89 90 top
RC46  10K_0402_5%~D  [R_0402]  100.58 47.08 180 bottom
RC47  10K_0402_5%~D  [R_0402]  100.58 48.02 180 bottom
RC48  0_0402_5%  [R0402_0OHM]  102.46 42.69 180 bottom
RC49  0_0402_5%  [R0402_0OHM]  102.46 41.8 180 bottom
RC50  10K_0402_5%~D  [R_0402]  135.35 66.53 90 top
RC52  10K_0402_5%~D  [R_0402]  136.31 66.53 90 top
RC53  0_0402_5%  [R0402_0OHM]  99.6 42.3 180 bottom
RC54  0_0402_5%  [R0402_0OHM]  99.6 41.4 180 bottom
RC55  10K_0402_5%~D  [R_0402]  113.77 79.06 270 bottom
RC58  22_0402_5%~D  [R_0402]  124.03 86.64 90 top
RC59  0_0402_5%  [R0402_0OHM]  98.7 45.9 180 bottom
RC60  0_0402_5%  [R0402_0OHM]  98.7 46.79 180 bottom
RC61  22_0402_5%~D  [R_0402]  124.64 83.94 180 top
RC63  22_0402_5%~D  [R_0402]  133.5 85.14 0 top
RC64  22_0402_5%~D  [R_0402]  137.18 63.57 90 top
RC65  0_0402_5%  [R0402_0OHM]  134.52 63.57 90 top
RC66  22_0402_5%~D  [R_0402]  138.07 63.57 90 top
RC67  1.8K_0402_1%  [R_0402]  162.15 27.18 270 top
RC68  2_0402_1%  [R_0402]  160.37 25.4 270 top
RC69  1.8K_0402_1%  [R_0402]  160.37 26.27 90 top
RC70  10K_0402_5%~D  [R_0402]  133.64 77.98 270 bottom
RC72  0_0402_5%  [R0402_0OHM]  107.91 81.02 0 bottom
RC73  330K_0402_1%~D  [R_0402]  135.67 73.98 270 bottom
RC74  10K_0402_5%~D  [R_0402]  116.94 82.05 270 top
RC76  8.2K_0402_5%~D  [R_0402]  103.22 80.47 90 bottom
RC78  330K_0402_1%~D  [R_0402]  134.34 74.04 270 bottom
RC79  0_0402_5%~D  [R_0402]  133.58 67.44 270 top
RC80  8.2K_0402_5%~D  [R_0402]  112.23 80.76 0 bottom
RC81  8.2K_0402_5%~D  [R_0402]  102.27 81.41 270 bottom
RC82  0_0402_5%~D  [R_0402]  132.76 77.98 180 bottom
RC83  24.9_0402_1%~D  [R_0402]  159.49 26.27 90 top
RC84  0_0402_5%~D  [R_0402]  137.01 73.07 90 bottom
RC85  100_0402_1%~D  [R_0402]  103.99 81.19 90 top
RC86  0_0402_5%  [R0402_0OHM]  117.63 78.16 0 bottom
RC87  0_0402_5%  [R0402_0OHM]  135.36 78.36 270 bottom
RC88  0_0402_5%  [R0402_0OHM]  133.51 71 270 bottom
RC90  0_0402_5%  [R0402_0OHM]  123.42 81.09 270 bottom
RC91  0_0402_5%  [R0402_0OHM]  126.15 81.09 270 bottom
RC92  0_0402_5%  [R0402_0OHM]  125.2 81.09 270 bottom
RC93  0_0402_5%  [R0402_0OHM]  134.47 67.44 270 top
RC94  0_0402_5%  [R0402_0OHM]  132.76 77.09 180 bottom
RC95  0_0402_5%~D  [R_0402]  103.91 15.42 0 bottom
RC96  0_0402_5%~D  [R_0402]  101.75 18.15 0 bottom
RC97  0_0402_5%~D  [R_0402]  101.75 15.42 0 bottom
RC98  10K_0402_5%~D  [R_0402]  118.54 79.05 180 bottom
RC99  1K_0402_1%~D  [R_0402]  133.65 4.25 180 top
RC100  0_0402_5%  [R0402_0OHM]  133.51 86.15 90 top
RC101  0_0402_5%~D  [R_0402]  112.19 16.5 180 bottom
RC102  1K_0402_1%~D  [R_0402]  135.27 15.09 90 top
RC103  0_0402_5%~D  [R_0402]  103.91 18.15 0 bottom
RC104  0_0402_5%~D  [R_0402]  104.83 17.2 180 bottom
RC105  1K_0402_1%~D  [R_0402]  140.92 16.01 270 top
RC106  1K_0402_1%~D  [R_0402]  141.81 16.01 270 top
RC107  0_0402_5%  [R0402_0OHM]  140.04 16.01 270 top
RC108  0_0402_5%  [R0402_0OHM]  137.96 16.01 270 top
RC109  1K_0402_1%~D  [R_0402]  137.22 3.41 90 top
RC110  0_0402_5%  [R0402_0OHM]  136.16 16.01 270 top
RC111  0_0402_5%  [R0402_0OHM]  134.34 16.01 270 top
RC112  0_0402_5%  [R0402_0OHM]  133.45 16.01 270 top
RC113  49.9_0402_1%~D  [R_0402]  113.77 17.95 90 bottom
RC114  62_0402_5%~D  [R_0402]  112.88 17.95 90 bottom
RC115  10K_0402_5%~D  [R_0402]  100.95 25.96 180 bottom
RC116  1K_0402_1%~D  [R_0402]  102.21 82.11 270 top
RC117  56_0402_5%~D  [R_0402]  112.75 20.3 90 bottom
RC118  51_0402_1%~D  [R_0402]  100.29 23.68 0 bottom
RC119  51_0402_1%~D  [R_0402]  100.3 22.74 270 bottom
RC120  51_0402_1%~D  [R_0402]  113.76 20.3 90 bottom
RC121  0_0402_5%~D  [R_0402]  111.1 18.86 270 bottom
RC122  51_0402_1%~D  [R_0402]  110.08 19.85 90 bottom
RC123  0_0402_5%~D  [R_0402]  104.82 14.48 180 bottom
RC124  0_0402_5%~D  [R_0402]  101.76 14.42 270 bottom
RC125  200_0402_1%~D  [R_0402]  131.06 27.17 315 top
RC126  2_0402_1%  [R_0402]  156.05 10.42 270 top
RC127  51_0402_1%~D  [R_0402]  102.72 13.5 90 bottom
RC128  24.9_0402_1%~D  [R_0402]  155.17 11.28 90 top
RC129  121_0402_1%  [R_0402]  131.58 30.02 315 top
RC130  1.8K_0402_1%  [R_0402]  157.01 12.2 270 top
RC131  51_0402_1%~D  [R_0402]  112.19 14.66 180 bottom
RC132  1.8K_0402_1%  [R_0402]  156.05 11.28 90 top
RC133  100_0402_1%~D  [R_0402]  131.06 25.78 315 top
RC134  24.9_0402_1%~D  [R_0402]  111.44 53.76 90 top
RC135  0_0402_5%~D  [R_0402]  111.28 15.55 0 bottom
RC136  10K_0402_5%~D  [R_0402]  131.66 64.58 0 top
RC137  100K_0402_5%~D  [R_0402]  110.4 83.42 90 top
RC138  10K_0402_5%~D  [R_0402]  120.12 75.61 90 bottom
RC139  0_0402_5%~D  [R_0402]  103.22 68.58 270 bottom
RC140  10K_0402_5%~D  [R_0402]  107.8 83.42 90 top
RC141  0_0402_5%~D  [R_0402]  132.55 24.37 180 bottom
RC142  0_0402_5%  [R0402_0OHM]  132.56 16.01 270 top
RC143  0_0402_5%~D  [R_0402]  99.08 28.69 0 top
RC144  0_0402_5%~D  [R_0402]  137.06 78.29 0 bottom
RC145  0_0402_5%~D  [R_0402]  130.09 70.4 90 bottom
RC146  10K_0402_5%~D  [R_0402]  110.59 90.81 270 top
RC147  100K_0402_5%~D  [R_0402]  95.53 68.51 0 bottom
RC148  10K_0402_5%~D  [R_0402]  115.48 73.98 270 bottom
RC149  100K_0402_5%~D  [R_0402]  95.53 69.4 0 bottom
RC152  100K_0402_5%~D  [R_0402]  99.79 67.06 270 bottom
RC153  100K_0402_5%~D  [R_0402]  95.53 67.62 0 bottom
RC154  1K_0402_1%~D  [R_0402]  113.41 64.77 90 top
RC155  100K_0402_5%~D  [R_0402]  98.89 65.14 0 bottom
RC156  100K_0402_5%~D  [R_0402]  98.91 67.06 270 bottom
RC157  0_0402_5%~D  [R_0402]  95.65 38.86 180 top
RC158  100K_0402_5%~D  [R_0402]  101.02 69.52 180 bottom
RC159  22.6_0402_1%~D  [R_0402]  132.46 61.81 0 top
RC160  0_0402_5%~D  [R_0402]  120.52 3.1 180 bottom
RC161  3.01K_0402_1%~D  [R_0402]  99.53 50.47 0 top
RC162  0_0402_5%~D  [R_0402]  109.61 85.55 180 top
RC163  0_0402_5%  [R0402_0OHM]  99.53 51.36 0 top
RC164  0_0402_5%~D  [R_0402]  116.81 3.09 0 top
RC165  0_0402_5%~D  [R_0402]  97 38.86 0 bottom
RC166  10K_0402_5%~D  [R_0402]  111.29 83.42 90 top
RC168  49.9_0402_1%~D  [R_0402]  132.74 59.55 0 top
RC169  10K_0402_5%~D  [R_0402]  121.07 73.32 90 bottom
RC170  100K_0402_5%~D  [R_0402]  121.07 75.54 90 bottom
RC172  0_0402_5%  [R0402_0OHM]  99.91 24.63 0 bottom
RC173  2_0402_1%  [R_0402]  158.98 11.28 90 top
RC174  0_0402_5%  [R0402_0OHM]  110.72 76.46 270 bottom
RC175  10K_0402_5%~D  [R_0402]  121.2 81.09 270 bottom
RC176  0_0402_5%  [R0402_0OHM]  109.76 76.46 270 bottom
RC179  0_0402_5%~D  [R_0402]  95.65 39.75 180 top
RC180  0_0402_5%  [R0402_0OHM]  124.31 81.09 270 bottom
RC181  0_0402_5%  [R0402_0OHM]  122.47 80.18 90 bottom
RC183  100K_0402_5%~D  [R_0402]  111.73 74.24 270 bottom
RC184  0_0402_5%~D  [R_0402]  120.52 4.09 180 bottom
RC185  100K_0402_5%~D  [R_0402]  112.2 70.29 180 top
RC186  499_0402_1%~D  [R_0402]  119.54 85.67 270 top
RC187  0_0402_5%~D  [R_0402]  116.23 69.41 90 top
RC188  0_0402_5%~D  [R_0402]  116.81 4.08 0 top
RC189  100K_0402_5%~D  [R_0402]  208.13 138.54 90 top
RC190  1K_0402_1%~D  [R_0402]  114.65 82.11 270 top
RC191  100K_0402_5%~D  [R_0402]  208.13 137.61 270 top
RC192  499_0402_1%~D  [R_0402]  118.21 85.67 270 top
RC193  10K_0402_5%~D  [R_0402]  103.98 83.42 90 top
RC194  0_0402_5%  [R0402_0OHM]  111.86 21.21 270 bottom
RC195  24.9_0402_1%~D  [R_0402]  159.93 10.35 270 top
RC196  0_0402_5%~D  [R_0402]  97 39.75 0 bottom
RC197  10K_0402_5%~D  [R_0402]  132.87 68.57 0 top
RC198  100K_0402_5%~D  [R_0402]  120.43 84.75 90 top
RC199  100K_0402_5%~D  [R_0402]  106.84 84.33 270 top
RC204  0_0402_5%  [R0402_0OHM]  111.99 18.86 270 bottom
RC206  10K_0402_5%~D  [R_0402]  134.4 75 270 top
RC208  0_0402_5%  [R0402_0OHM]  109.96 23.05 270 bottom
RC209  0_0402_5%  [R0402_0OHM]  101.26 22.74 270 bottom
RC211  0_0402_5%  [R0402_0OHM]  136.19 74.73 180 top
RC217  1.8K_0402_1%  [R_0402]  157.96 12.2 270 top
RC218  10K_0402_5%~D  [R_0402]  104.94 83.42 90 top
RC221  1.8K_0402_1%  [R_0402]  158.98 10.35 270 top
RC222  1K_0402_1%~D  [R_0402]  120.12 74.3 270 bottom
RC230  10K_0402_5%~D  [R_0402]  117.33 80.76 180 bottom
RC232  1K_0402_1%~D  [R_0402]  119.61 21.15 270 bottom
RC233  1K_0402_1%~D  [R_0402]  118.72 21.15 270 bottom
RC235  49.9_0402_1%~D  [R_0402]  117.13 25.2 270 top
RC236  8.2K_0402_1%  [R_0402]  100.88 59.67 90 bottom
RC237  49.9_0402_1%~D  [R_0402]  132.42 59.55 0 bottom
RC238  1K_0402_1%~D  [R_0402]  119.32 31.37 90 top
RC239  1K_0402_1%~D  [R_0402]  116.43 31.5 180 top
RC240  1K_0402_1%~D  [R_0402]  117.39 21.34 270 top
RC241  1K_0402_1%~D  [R_0402]  117.45 21.15 270 bottom
RC242  0_0603_5%~D  [R_0603]  99.6 29.9 180 bottom
RC243  1K_0402_5%~D  [R_0402]  141.63 69.21 0 top
RC244  75_0402_1%~D  [R_0402]  115.02 17.01 0 bottom
RC245  0_0402_5%  [R0402_0OHM]  100.04 28.69 0 bottom
RC246  0_0402_5%  [R0402_0OHM]  98.26 28.69 0 bottom
RC247  0_0402_5%  [R0402_0OHM]  100.04 27.8 0 bottom
RC248  43_0402_5%~D  [R_0402]  115.92 18.86 270 bottom
RC249  110_0402_1%~D  [R_0402]  115.03 17.95 90 bottom
RC250  100_0402_1%~D  [R_0402]  99.08 27.74 0 top
RC253  150_0402_1%~D  [R_0402]  110.97 19.85 90 bottom
RC254  0_0805_5%  [R0805_0OHM]  94.06 61.27 0 top
RC255  10K_0402_5%~D  [R_0402]  98.26 26.91 0 bottom
RC256  10K_0402_5%~D  [R_0402]  99.17 27.8 180 bottom
RC258  10K_0402_5%~D  [R_0402]  110.91 22.14 90 bottom
RC259  10K_0402_5%~D  [R_0402]  100.95 26.91 180 bottom
RC260  100_0402_1%~D  [R_0402]  111.67 25.02 270 top
RC261  0_0402_5%  [R0402_0OHM]  137.31 59.38 180 top
RC262  0_0805_5%  [R0805_0OHM]  98.56 71.37 0 top
RC263  0_0402_5%  [R0402_0OHM]  139.12 67.75 180 top
RC264  0_0402_5%~D  [R_0402]  137.31 58.49 180 top
RC265  0_0402_5%~D  [R_0402]  128.24 81.6 270 top
RC267  0_0402_5%  [R0402_0OHM]  129.19 81.6 270 top
RC272  0_0402_5%~D  [R_0402]  120.62 64.77 180 top
RC275  5.11_0402_1%~D  [R_0402]  137.3 56.29 180 top
RC276  0_0603_5%~D  [R_0603]  98.84 64.44 270 top
RC279  0_0402_5%  [R0402_0OHM]  186.74 17.42 270 top
RC280  51_0402_1%~D  [R_0402]  135.43 3.42 90 top
RC282  10K_0402_5%~D  [R_0402]  103.1 82.11 270 top
RC283  1K_0402_1%~D  [R_0402]  102.32 70.41 0 bottom
RC284  10K_0402_5%~D  [R_0402]  100.81 82.11 270 top
RC285  20K_0402_5%~D  [R_0402]  102.32 69.52 0 bottom
RC287  1K_0402_1%~D  [R_0402]  104.94 85.26 90 top
RC288  1K_0402_1%~D  [R_0402]  103.24 71.36 180 bottom
RC289  10K_0402_5%~D  [R_0402]  105.32 71.44 270 bottom
RC290  10K_0402_5%~D  [R_0402]  104.86 82.11 270 top
RC291  10K_0402_5%~D  [R_0402]  122.02 75.54 90 bottom
RC292  10K_0402_5%~D  [R_0402]  111.49 90.81 270 top
RC297  1M_0402_5%~D  [R_0402]  172.3 115.5 0 top
RC305  10K_0402_5%~D  [R_0402]  106.96 86.99 0 top
RC306  10K_0402_5%~D  [R_0402]  115.48 76.2 270 bottom
RC315  10K_0402_5%~D  [R_0402]  113.96 70.28 180 top
RC324  10K_0402_5%~D  [R_0402]  98.92 69.52 180 bottom
RD1  0_0402_5%  [R0402_0OHM]  172.31 7.03 90 top
RD3  470_0402_5%~D  [R_0402]  187.63 17.42 270 top
RD5  0_0402_5%  [R0402_0OHM]  175.66 70.54 0 top
RD6  0_0402_5%  [R0402_0OHM]  174.61 70.54 180 top
RD7  0_0402_5%  [R0402_0OHM]  162.6 6.96 90 top
RD10  0_0402_5%  [R0402_0OHM]  163.18 71.68 180 top
RD11  0_0402_5%  [R0402_0OHM]  159.36 71.67 90 top
RD12  0_0402_5%  [R0402_0OHM]  182.79 49 90 top
RD13  0_0402_5%  [R0402_0OHM]  175.04 50.8 270 top
RE4  10_0402_1%~D  [R_0402]  170.3 163.54 90 top
RE5  10_0402_1%~D  [R_0402]  167.42 164.53 270 top
RP1  2.2K_0804_8P4R_5%  [RP_0804_8P4R]  95.15 64.9 0 bottom
RP2  10K_8P4R_5%  [RP_0804_8P4R]  136.69 119.26 180 top
RP3  10K_8P4R_5%  [RP_0804_8P4R]  112.62 85.26 0 top
RP4  4.7K_8P4R_5%  [RP_0804_8P4R]  146.58 113.79 270 top
RP5  100K_0804_8P4R_5%  [RP_0804_8P4R]  158.92 98.43 180 top
RP6  2.2K_0804_8P4R_5%  [RP_0804_8P4R]  127.92 108.88 0 top
RP7  2.2K_0804_8P4R_5%  [RP_0804_8P4R]  133.52 105.03 180 top
RP8  2.2K_0804_8P4R_5%  [RP_0804_8P4R]  107.43 71.88 270 bottom
RP9  10K_8P4R_5%  [RP_0804_8P4R]  112.89 75.5 270 bottom
RP10  10K_8P4R_5%  [RP_0804_8P4R]  116.87 85.08 270 top
RP11  10K_8P4R_5%  [RP_0804_8P4R]  116.64 75.5 270 bottom
RP12  10K_8P4R_5%  [RP_0804_8P4R]  131.92 73.7 0 top
RP13  10K_8P4R_5%  [RP_0804_8P4R]  128.93 70.66 90 bottom
RP14  10K_8P4R_5%  [RP_0804_8P4R]  128.45 80.51 270 bottom
RP15  2.2K_0804_8P4R_5%  [RP_0804_8P4R]  133.52 108.14 180 top
RP16  10K_8P4R_5%  [RP_0804_8P4R]  141.5 113.85 270 top
RP17  100K_0804_8P4R_5%  [RP_0804_8P4R]  141.63 96.26 270 top
RP18  100K_0804_8P4R_5%  [RP_0804_8P4R]  154.73 103.64 180 top
RTCD1  -  [BAT54CW_SOT323-3]  41.86 63.94 90 bottom
RTCR1  1K_0402_1%~D  [R_0402]  41.16 60.95 90 bottom
RV2  200_0402_1%~D  [R_0402]  55.23 71.37 180 bottom
RV29  10K_0402_5%~D  [R_0402]  74.27 78.08 90 top
RV34  100K_0402_5%~D  [R_0402]  67.53 90.92 0 top
RV35  100K_0402_5%~D  [R_0402]  70.84 94.94 270 top
RV45  2.2K_0402_5%~D  [R_0402]  60.62 102.43 270 bottom
RV46  2.2K_0402_5%~D  [R_0402]  61.51 102.43 270 bottom
RV48  100K_0402_5%~D  [R_0402]  70.27 98.53 90 bottom
RV49  2.2K_0402_5%~D  [R_0402]  70.78 104.52 270 bottom
RV50  2.2K_0402_5%~D  [R_0402]  70.78 105.58 90 bottom
RV73  0_0402_5%~D  [R_0402]  74.88 95.61 0 top
RV74  0_0402_5%~D  [R_0402]  74.88 94.73 0 top
RV75  0_0402_5%~D  [R_0402]  79.18 92.42 90 bottom
RV76  0_0402_5%~D  [R_0402]  80.07 93.33 270 bottom
RV88  10K_0402_5%  [R_0402]  70.12 69.63 0 bottom
RV89  10K_0402_1%~D  [R_0402]  60.62 99.7 270 bottom
RV90  10K_0402_1%~D  [R_0402]  58.84 99.7 270 bottom
RV92  10K_0402_1%~D  [R_0402]  59.73 99.7 270 bottom
RV93  10K_0402_1%~D  [R_0402]  77.01 95.37 180 bottom
RV94  10K_0402_1%~D  [R_0402]  76.1 96.26 0 bottom
RV2404  0_0402_5%  [R0402_0OHM]  67.53 89.65 0 top
RV2427  0_0402_5%  [R0402_0OHM]  72.41 78.1 0 top
RV2433  10K_0402_5%~D  [R_0402]  71.14 79.81 0 top
RV2435  10K_0402_5%~D  [R_0402]  69.24 75.94 0 top
RV2436  10K_0402_5%~D  [R_0402]  76.1 90.86 0 bottom
RV2437  10K_0402_1%~D  [R_0402]  34.9 69.79 270 bottom
RV2438  10K_0402_1%~D  [R_0402]  34.58 97.77 90 bottom
RV2439  10K_0402_1%~D  [R_0402]  33.94 69.79 270 bottom
RV2440  10K_0402_1%~D  [R_0402]  33.63 97.77 90 bottom
RV2441  10K_0402_5%~D  [R_0402]  61.51 99.7 270 bottom
RV2442  10K_0402_5%~D  [R_0402]  62.39 98.78 90 bottom
RV2444  10K_0402_5%~D  [R_0402]  63.85 94.94 270 top
RV2446  10K_0402_5%~D  [R_0402]  71.6 92.33 270 top
RV2447  10K_0402_5%~D  [R_0402]  27.09 86.21 90 bottom
RV2647  10K_0402_1%~D  [R_0402]  69.9 93.78 180 top
RV2648  10K_0402_1%~D  [R_0402]  68.99 94.67 0 top
RV2649  10K_0402_1%~D  [R_0402]  77.01 93.59 180 bottom
RV2650  10K_0402_1%~D  [R_0402]  76.1 94.48 0 bottom
RV2651  10K_0402_1%~D  [R_0402]  76.69 93.34 180 top
RV2652  10K_0402_1%~D  [R_0402]  75.78 92.45 0 top
RV2653  10K_0402_1%~D  [R_0402]  77.01 92.7 180 bottom
RV2654  10K_0402_1%~D  [R_0402]  76.1 91.75 0 bottom
RV2703  2.49K_0402_1%~D  [R_0402]  47.98 71.67 90 bottom
RV2704  60.4_0402_1%~D  [R_0402]  52.56 91.68 180 top
RV2705  60.4_0402_1%~D  [R_0402]  56.68 89.01 90 top
RV2706  162_0402_1%  [R_0402]  36.5 97.72 180 bottom
RV2707  80.6_0402_1%~D  [R_0402]  36.49 99.51 270 bottom
RV2708  80.6_0402_1%~D  [R_0402]  35.6 99.51 270 bottom
RV2709  1.33K_0402_1%~D  [R_0402]  33.56 100.46 270 top
RV2710  1.33K_0402_1%~D  [R_0402]  33.55 98.67 0 top
RV2711  1.33K_0402_1%~D  [R_0402]  35.34 100.46 270 top
RV2712  1.33K_0402_1%~D  [R_0402]  35.33 98.67 0 top
RV2713  1.33K_0402_1%~D  [R_0402]  33.83 68.06 180 top
RV2714  1.33K_0402_1%~D  [R_0402]  32.92 68.95 0 top
RV2715  1.33K_0402_1%~D  [R_0402]  33.26 82.22 180 top
RV2716  1.33K_0402_1%~D  [R_0402]  32.34 83.37 0 top
RV2717  162_0402_1%  [R_0402]  37.32 69.9 180 top
RV2718  80.6_0402_1%~D  [R_0402]  37.31 68.11 90 top
RV2719  80.6_0402_1%~D  [R_0402]  36.42 68.11 90 top
RV2720  40.2_0402_1%~D  [R_0402]  56.09 93.78 0 top
RV2721  42.2_0402_1%  [R_0402]  54 93.97 0 top
RV2722  51.1_0402_1%  [R_0402]  54 94.86 0 top
RV2723  40.2K_0402_1%~D  [R_0402]  69.11 92.13 0 top
RV2805  100K_0402_5%~D  [R_0402]  24.91 98.8 0 bottom
RV2906  243_0402_1%~D  [R_0402]  32.74 98.68 270 bottom
RV2907  243_0402_1%~D  [R_0402]  35.21 68.94 90 top
RV2908  243_0402_1%~D  [R_0402]  26.14 87.13 270 bottom
RV2909  243_0402_1%~D  [R_0402]  33.49 85.65 0 top
RZ10  22_0402_5%~D  [R_0402]  28.63 100.19 180 top
RZ11  22_0402_5%~D  [R_0402]  31.17 102.73 180 top
RZ40  22_0402_5%~D  [R_0402]  59.02 70.79 0 top
RZ41  22_0402_5%~D  [R_0402]  64.23 72.27 270 top
SW5  EVQPLHA15_4P  [SW_EVQPLHA15_4P]  190.6 131.25 180 top
SW6  EVQPLHA15_4P  [SW_EVQPLHA15_4P]  39.57 21.39 180 bottom
T92  PAD~D  [TPC12]  178 144.11 0 top
T93  PAD~D  [TPC12]  176.95 143.09 0 top
T171  PAD  [TPC12]  54.52 92.76 0 top
T186  PAD  [TPC12]  71.31 70.61 180 bottom
T187  PAD  [TPC12]  68.65 74.92 0 top
T188  PAD  [TPC12]  69.57 71.49 180 bottom
T189  PAD  [TPC12]  68.48 69.77 180 bottom
T190  PAD  [TPC12]  73.01 69.75 180 bottom
T191  PAD  [TPC12]  114.4 80.72 180 bottom
U1  -  [W25Q64FVSSIQ_SO8]  38.65 15.8 270 bottom
U2  -  [W25Q32FVSSIQ_SO8]  16.86 11.99 90 bottom
U5  -  [74AUP1G07GW_TSSOP5]  190.14 35.35 0 top
U6  IDTVMM2320BKG8_BGA168  [IDTVMM2320BKG8_BGA_168P-NH]  117.17 100.21 90 top
U7  W25X10CLSNIG_SO8  [W25X10BVSNIG_SO8]  99.58 88.64 90 top
U11  PI3C3125LEX_TSSOP14~D  [PI3C3125LEX_TSSOP14]  145.66 139.9 0 top
U13  PI3C3125LEX_TSSOP14~D  [PI3C3125LEX_TSSOP14]  151.25 139.97 0 top
U15  LNG3DMTR_LGA16_3X3~D  [LNG3DMTR_LGA16_3X3]  161.22 125.04 90 top
U17  -  [ALC3226-CG_QFN48_7X7]  252.68 156.26 0 bottom
U18  TPS22966DPUR_SON14_2X3~D  [TPS22966DPUR_SON14_2X3]  251.81 171.2 180 top
U19  TPS22966DPUR_SON14_2X3~D  [TPS22966DPUR_SON14_2X3]  79.89 87.35 270 bottom
U20  TC7SH08FU_SSOP5~D  [TC7SH08FU_SSOP5]  174.04 146.36 180 top
U21  WGI218LM-SLJK3A-B1_QFN48_6X6  [WGI218LM-QQ89-B0_QFN48_6X6]  176.5 135.66 0 top
U22  -  [APE8988Y_SOT26-6]  199.67 166.68 90 top
U23  PI3L720ZHEX_TQFN42_9X3P5~D  [PI3L720ZHEX_TQFN42_9X3P5]  180.77 156.06 0 top
U24  TC7SH08FU_SSOP5~D  [TC7SH08FU_SSOP5]  181.38 144.33 0 top
U25  AT97SC3204-X4A12-ABF TSSOP 28P  [AT97SC3204-X2A14-AB_TSSOP28]  164.98 115.86 180 top
U27  OZ777FJ2LN_QFN48P_6X6  [OZ777FJ2LN_QFN48_6X6]  14.36 25.46 180 bottom
U28  SRV05-4.TCT_SOT23-6~D  [SRV05-4PTCT_SOT23-6]  234.07 161.84 180 top
U29  -  [APE8988Y_SOT26-6]  188.89 24.94 0 bottom
U30  TC7SH08FU_SSOP5~D  [TC7SH08FU_SSOP5]  218.27 133.66 0 top
U33  -  [APE8988Y_SOT26-6]  94.46 97.53 90 top
U34  -  [APE8988Y_SOT26-6]  89.18 109.4 90 top
U37  ECE5048-LZY_DQFN132_11X11~D  [ECE5048-LZY_DQFN132_11X11]  171.23 103.04 180 top
U38  MEC5075-LZY-SAL00_DQFN132_11X11~D  [MEC5075-LZY_DQFN132_11X11]  141.39 98.36 0 top
U39  PI3V713-AZLEX_TQFN32_6X3~D  [PI3V713-AZLEX_TQFN32_6X3]  157.17 150.68 0 top
U41  RT9818A-44GU3_SC70-3~D  [RT9818A-44GU3_SC70-3]  145.96 119.69 0 top
U42  TC7SH08FU_SSOP5~D  [TC7SH08FU_SSOP5]  144.05 117.9 90 top
U43  TPS22966DPUR_SON14_2X3~D  [TPS22966DPUR_SON14_2X3]  89.44 73.71 270 top
U45  TPS22966DPUR_SON14_2X3~D  [TPS22966DPUR_SON14_2X3]  85.26 19.9 0 bottom
U46  TPS22966DPUR_SON14_2X3~D  [TPS22966DPUR_SON14_2X3]  215.36 151.81 270 top
U47  TC7SH08FU_SSOP5~D  [TC7SH08FU_SSOP5]  192.88 90.21 90 top
U51  TPS22966DPUR_SON14_2X3~D  [TPS22966DPUR_SON14_2X3]  210.28 139.24 270 top
U52  RTD2136R-CG_QFN48_6X6  [RTD2136S-VE-CG_QFN48_6X6]  100.96 109.79 0 top
U83  -  [PS8713BTQFN24GTR2_TQFN24_4X4]  298.7 167.79 0 top
U86  TC7SH08FU_SSOP5~D  [TC7SH08FU_SSOP5]  97.11 94.55 0 top
U87  TC7SH08FU_SSOP5~D  [TC7SH08FU_SSOP5]  100.86 94.61 0 top
U90  -  [USX2064-AEZG-TR_QFN36_6X6]  175.2 119.4 90 top
U91  PI2DBS6212ZHEX TQFN 28P  [PI2DBS212ZHEX_TQFN28_5P5X3P5]  160.55 137.56 270 top
U93  -  [PI5A3157CEX_SC70-6]  101.05 6.91 0 bottom
U94  -  [APE8939GN3_DFN8_3X3]  95.41 79.34 270 top
UC1  HASWELL-MCP-E-ULT_BGA1168  [HASWELL-MCP-E-ULT_BGA_1168P-T]  106.54 67.21 90 bottom
UC2  74AHC1G09GW_TSSOP5~D  [74AHC1G09GW_TSSOP5]  104.66 79.88 90 bottom
UC3  TC7SH08FU_SSOP5~D  [TC7SH08FU_SSOP5]  135.74 79.54 90 bottom
UC4  -  [74AUP1G07GW_TSSOP5]  138.4 70.49 270 top
UC5  -  [5V60034DCG8_SO8]  126.55 87.18 270 top
UC6  -  [74CBTLV3126BQ_DHVQFN14_2P5X3]  107.71 14.47 90 bottom
UC7  TC7SH08FU_SSOP5~D  [TC7SH08FU_SSOP5]  136.53 77.16 0 bottom
US1  -  [G547I2P81U_MSOP8]  26.16 68.61 180 bottom
UV1  N14M-GE-S-A2_FCBGA595~D  [N14M-GE-S-A2_FCBGA_595P]  72.67 95.15 180 bottom
UV4  MT41K256M16HA-107G-E_FBGA96~D  [MT41K256M16HA-125M-E_FBGA_96P]  41.66 88.51 90 bottom
UV5  MT41K256M16HA-107G-E_FBGA96~D  [MT41K256M16HA-125M-E_FBGA_96P]  41.66 94.91 270 top
UV6  MT41K256M16HA-107G-E_FBGA96~D  [MT41K256M16HA-125M-E_FBGA_96P]  41.67 72.76 90 bottom
UV7  MT41K256M16HA-107G-E_FBGA96~D  [MT41K256M16HA-125M-E_FBGA_96P]  41.67 79.16 270 top
UV14  TC7SH08FU_SSOP5~D  [TC7SH08FU_SSOP5]  74.33 76.46 270 top
Y1  27MHZ_12PF_+-20PPM_CRG3202712  [Y_X1E000021042600_4P]  126.38 93.87 0 top
